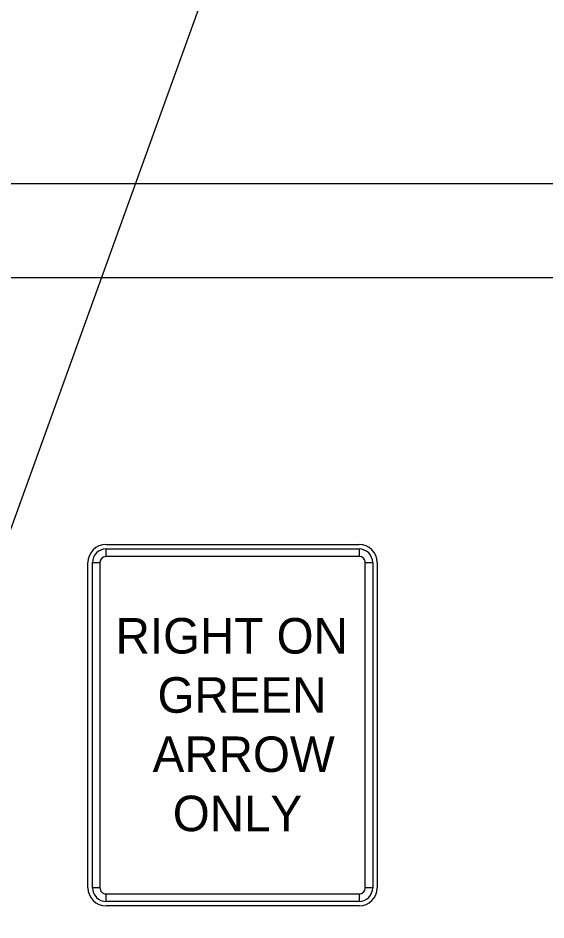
# Model space of a CAD drawing. Extents: x 660063 to 664816, y 641756 to 643817.
# Drawn here: x 661839.8 to 661905.5, y 642797 to 642909.3 of the extents above; entities that cross this region are included whole.
import ezdxf

# ---------------------------------------------------------------- set-up
doc = ezdxf.new("R2010")
doc.units = 0
for name, color, linetype in [('R_Border', 7, 'Continuous'), ('R_No Plot', 7, 'Continuous'), ('T_Drafting', 7, 'Continuous')]:
    doc.layers.add(name, color=color, linetype=linetype)

msp = doc.modelspace()

# ---------------------------------------------------------------- linework, layer by layer
at = {"layer": 'R_Border'}
msp.add_line((661447.99, 642876.97), (662396.53, 642876.97), dxfattribs=at)
at = {"layer": 'R_No Plot'}
msp.add_line((661410.79, 642888.66), (662410.79, 642888.66), dxfattribs=at)
msp.add_lwpolyline([(661410.77, 642888.66), (662410.79, 642888.66), (662410.79, 642248.64), (661410.77, 642248.64)], close=True, dxfattribs=at)
at = {"layer": 'T_Drafting'}
for p, q in [((661850.7, 642843.72), (661882.2, 642843.72)), ((661850.7, 642842.22), (661850.7, 642843.16)), ((661882.2, 642843.16), (661882.2, 642842.22)), ((661848.45, 642800.97), (661848.45, 642841.47)), ((661849.01, 642841.47), (661849.95, 642841.47)), ((661882.95, 642841.47), (661883.89, 642841.47)), ((661884.45, 642841.47), (661884.45, 642800.97)), ((661849.95, 642800.97), (661849.01, 642800.97)), ((661850.7, 642799.28), (661850.7, 642800.22)), ((661882.2, 642800.22), (661882.2, 642799.28)), ((661883.89, 642800.97), (661882.95, 642800.97)), ((661882.2, 642798.72), (661850.7, 642798.72))]:
    msp.add_line(p, q, dxfattribs=at)
msp.add_lwpolyline([(661903.35, 643024.49), (661786.96, 642702.02), (661273.12, 641816.18)], dxfattribs=at)
msp.add_lwpolyline([(661903.35, 643024.49), (661786.96, 642702.02), (661273.12, 641816.18)], dxfattribs=at)
msp.add_lwpolyline([(661903.35, 643024.49), (661786.96, 642702.02), (661273.12, 641816.18)], dxfattribs=at)
for points in [[(661882.2, 642842.22), (661850.7, 642842.22), (661850.7, 642843.16), (661882.2, 642843.16), (661882.2, 642842.22)], [(661849.95, 642841.47), (661849.95, 642800.97), (661849.01, 642800.97), (661849.01, 642841.47), (661849.95, 642841.47)], [(661882.95, 642800.97), (661882.95, 642841.47), (661883.89, 642841.47), (661883.89, 642800.97), (661882.95, 642800.97)], [(661850.7, 642800.22), (661882.2, 642800.22), (661882.2, 642799.28), (661850.7, 642799.28), (661850.7, 642800.22)]]:
    msp.add_lwpolyline(points, close=True, dxfattribs=at)
for centre, radius, start, end in [((661850.7, 642841.47), 2.25, 90, 180), ((661850.7, 642841.47), 1.69, 90.0002, 179.9998), ((661882.2, 642841.47), 2.25, 360, 90), ((661882.2, 642841.47), 1.69, 360, 90.0002), ((661850.7, 642841.47), 0.75, 90.0002, 179.9998), ((661882.2, 642841.47), 0.75, 360, 90.0002), ((661850.7, 642800.97), 2.25, 180, 270), ((661850.7, 642800.97), 1.69, 179.9998, 270.0001), ((661850.7, 642800.97), 0.75, 179.9998, 270.0001), ((661882.2, 642800.97), 2.25, 270, 360), ((661882.2, 642800.97), 1.69, 270.0001, 0.0003), ((661882.2, 642800.97), 0.75, 270.0001, 0.0003)]:
    msp.add_arc(centre, radius, start, end, dxfattribs=at)

# ---------------------------------------------------------------- texts
for s, p in [('RIGHT ON ', (661851.89, 642830.14)), ('GREEN', (661857.11, 642822.77)), ('ARROW', (661856.5, 642815.39)), ('ONLY', (661859.01, 642808.02))]:
    msp.add_text(s, height=4.422, rotation=360, dxfattribs=at).set_placement(p)

doc.saveas('drawing.dxf')
